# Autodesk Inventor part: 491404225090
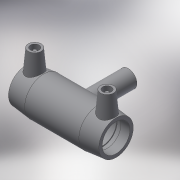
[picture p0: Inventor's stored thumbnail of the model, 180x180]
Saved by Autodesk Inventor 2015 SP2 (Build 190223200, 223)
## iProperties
Created: 2017-06
Part Number: 491404225090
Material: Generic
Description: PLASSON REDUCING TEE 225x90x225
Document SubType Name: Modeling
Designer: KIM
Mass: 57.3761 g
Surface Area: 241.06 cm^2
Volume: 57.3761 cm^3
Density: 1 g/cm^3
Appearance: Default
Author: KIM
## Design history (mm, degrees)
derived "491404.ipt"
feature "Solid1::491404.ipt"
tag "TaggingFeature1"
body "Solid1"
other parameters: "d0" = 494, "d1" = 225, "d2" = 293, "d3" = 122, "d4" = 98.8, "d5" = 263.7, "d6" = 213.75, "d7" = 225, "d8" = 168 deg, "d10" = 48.8, "d11" = 16.26667, "d13" = 494, "d14" = 17.6296, "d17" = 202.5, "d18" = 225, "d19" = 3.52592, "d20" = 168 deg, "d22" = 272.49, "d23" = 293, "d25" = 135 deg, "d26" = 345.8, "d30" = 15, "d31" = 197.6, "d34" = 5 deg, "d35" = 15, "d39" = 5 deg, "d41" = 4, "d42" = 14, "d43" = 0, "d45" = 4, "d46" = 6, "d47" = 0, "d51" = 0, "d52" = 72, "d54" = 0, "d55" = 263.7, "d56" = 293, "d57" = 172.9, "d58" = 135 deg, "d59" = 122, "d60" = 122, "d61" = 135 deg, "d72" = 224.77, "d73" = 112.385, "d75" = 94.5, "d77" = 0, "d78" = 72, "d80" = 0, "d82" = 73.5, "d83" = 0, "d84" = 3, "d85" = 0, "d86" = 40.66667, "d87" = 267.0402, "d88" = 16.26667, "d89" = 3, "d90" = 0, "d_" = 225, "L_" = 494, "L_1" = 122, "D_" = 293, "d_2" = 12
